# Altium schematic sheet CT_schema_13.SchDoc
size 391 x 385 mm
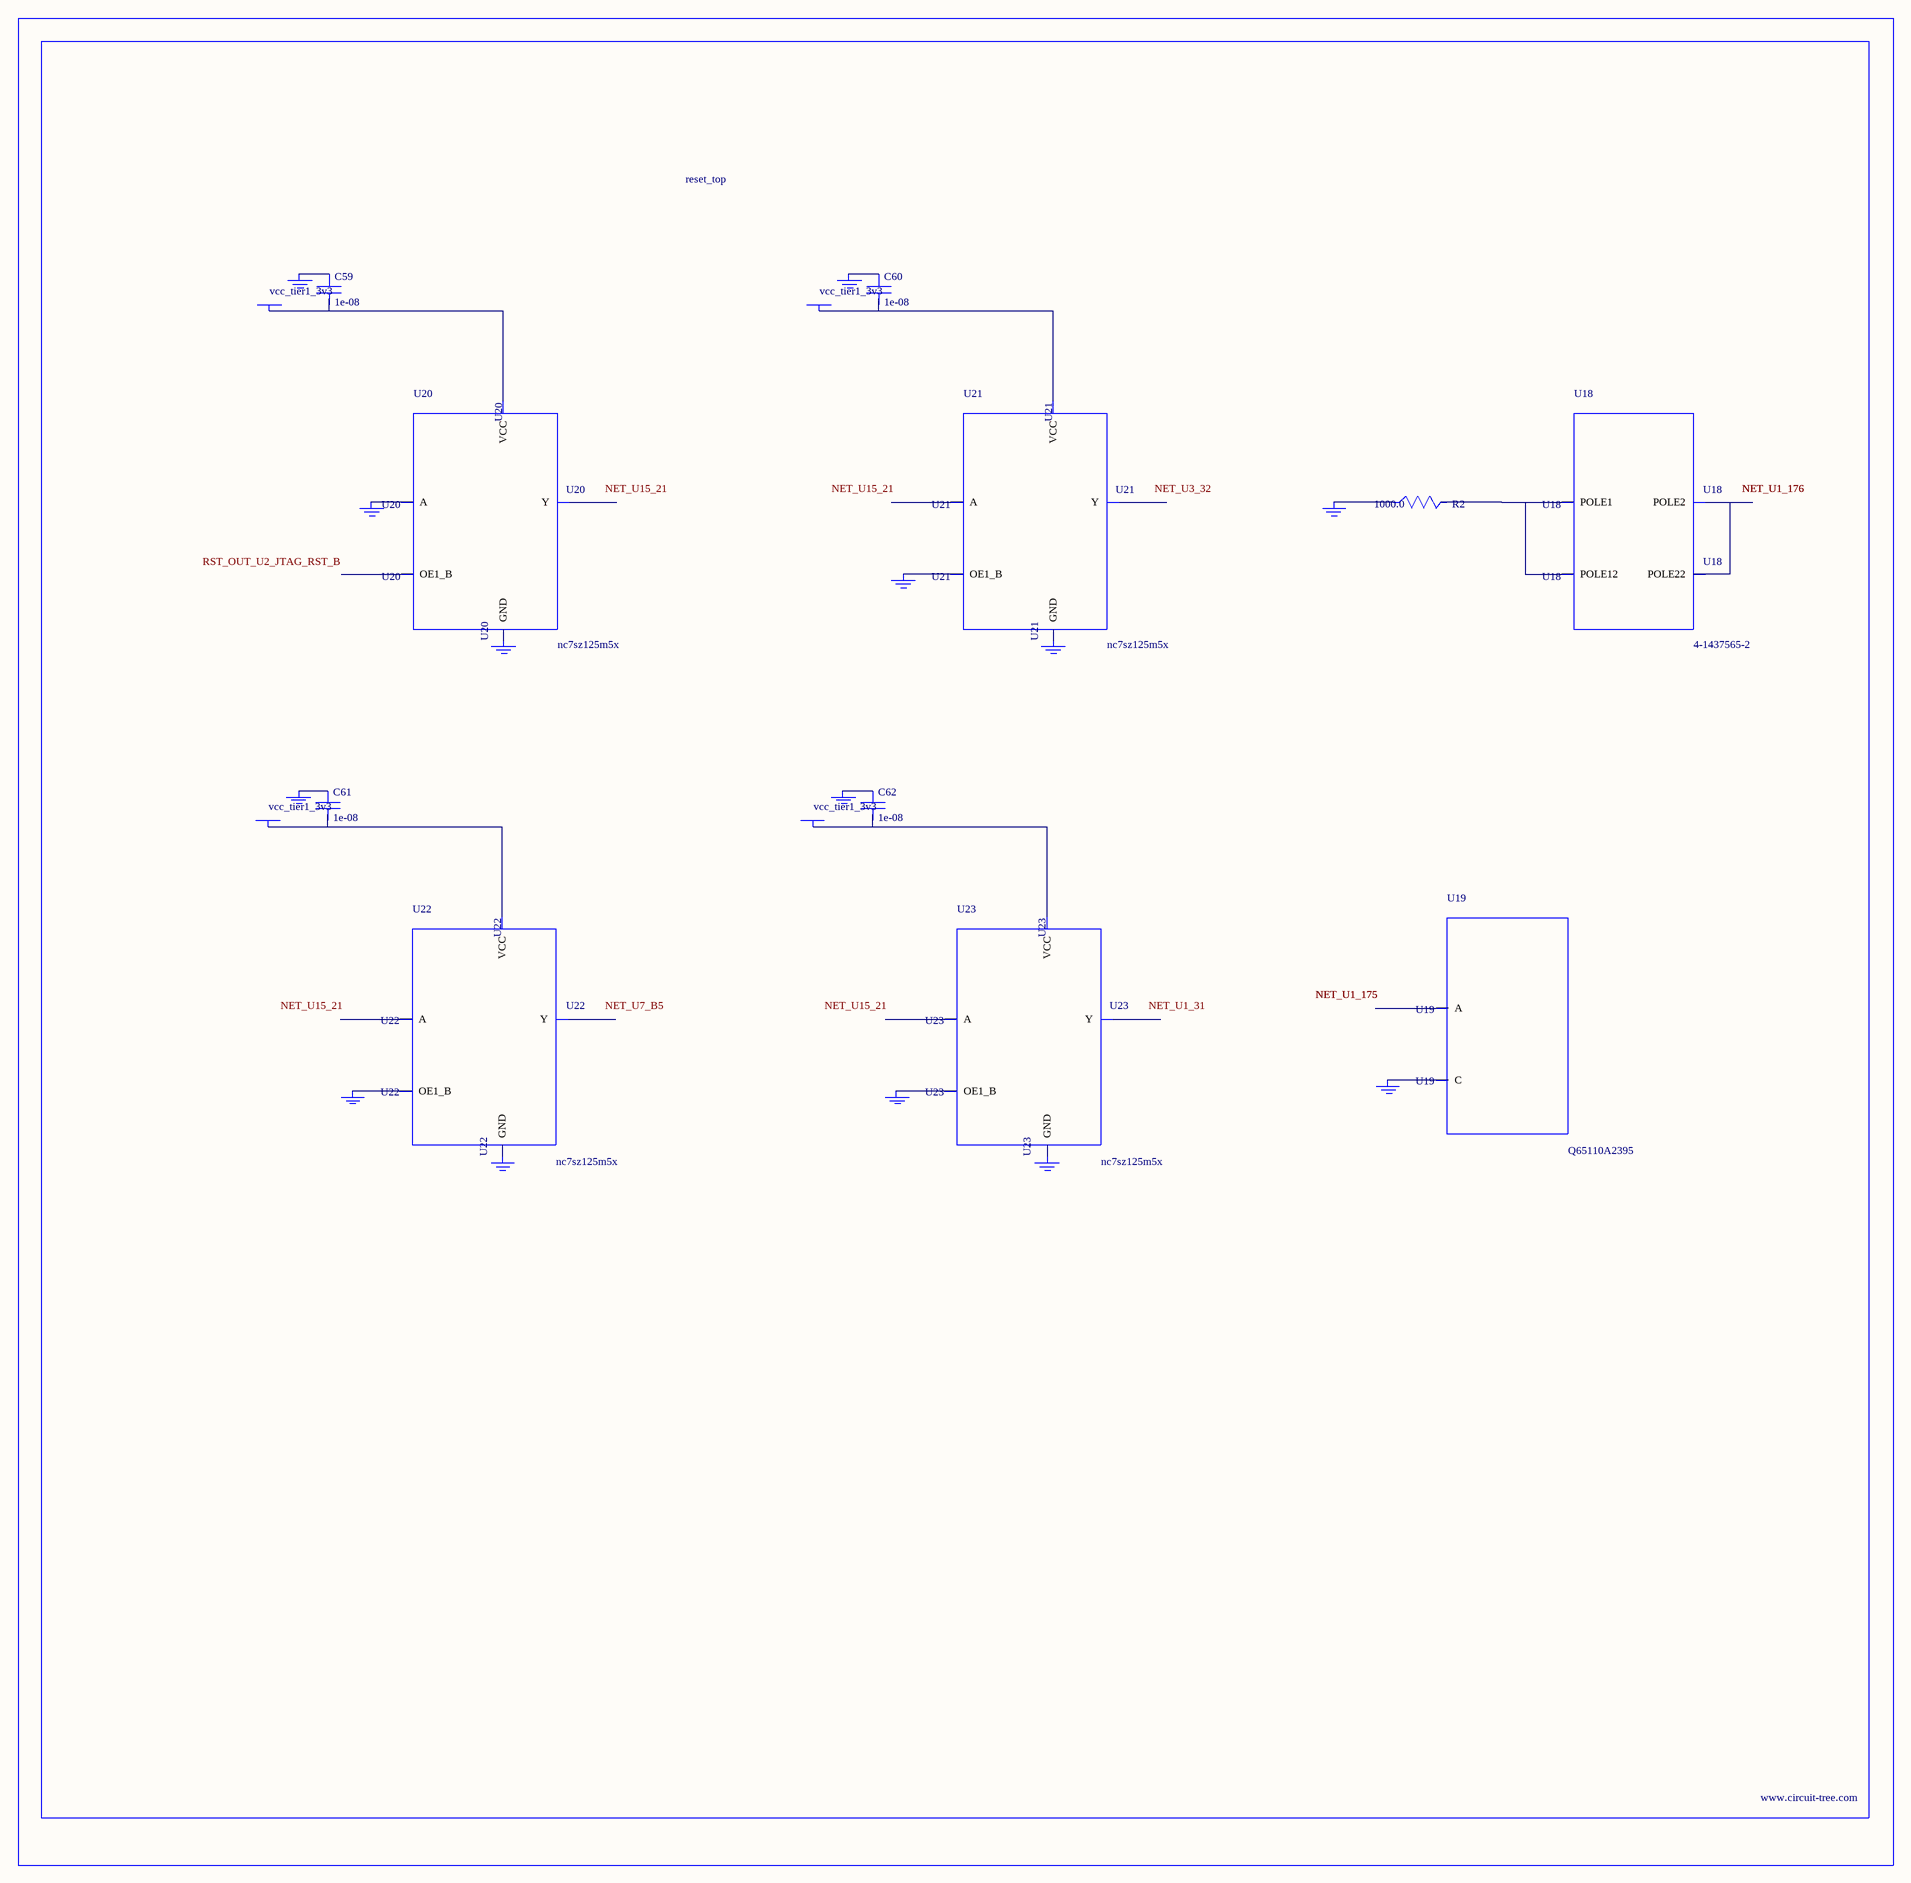
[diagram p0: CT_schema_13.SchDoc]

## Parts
BORDER12  (no value)
C59  1e-08  [C0402]
C60  1e-08  [C0402]
C61  1e-08  [C0402]
C62  1e-08  [C0402]
GND_INSTANCE_12_0  (no value)
GND_INSTANCE_12_1  (no value)
GND_INSTANCE_12_2  (no value)
GND_INSTANCE_12_3  (no value)
GND_INSTANCE_12_4  (no value)
GND_INSTANCE_12_5  (no value)
GND_INSTANCE_12_6  (no value)
GND_INSTANCE_12_7  (no value)
GND_INSTANCE_12_8  (no value)
GND_INSTANCE_12_9  (no value)
GND_INSTANCE_12_10  (no value)
GND_INSTANCE_12_11  (no value)
GND_INSTANCE_12_12  (no value)
GND_INSTANCE_12_13  (no value)
POWER_INSTANCE_12_0  vcc_tier1_3v3
POWER_INSTANCE_12_1  vcc_tier1_3v3
POWER_INSTANCE_12_2  vcc_tier1_3v3
POWER_INSTANCE_12_3  vcc_tier1_3v3
R2  1000.0  [R0603]
U18  4-1437565-2  [SW_4-1437565-2]
U19  Q65110A2395  [LGM67K-G1J2-24-Z]
U20  nc7sz125m5x  [NC7SZ125M5X]
U21  nc7sz125m5x  [NC7SZ125M5X]
U22  nc7sz125m5x  [NC7SZ125M5X]
U23  nc7sz125m5x  [NC7SZ125M5X]

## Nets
NetC59_1: C59.1 GND_INSTANCE_12_2.0(GND)
NetC59_2: C59.2 POWER_INSTANCE_12_0.0(PWR) U20.5(VCC)
NetC60_1: C60.1 GND_INSTANCE_12_5.0(GND)
NetC60_2: C60.2 POWER_INSTANCE_12_1.0(PWR) U21.5(VCC)
NetC61_1: C61.1 GND_INSTANCE_12_8.0(GND)
NetC61_2: C61.2 POWER_INSTANCE_12_2.0(PWR) U22.5(VCC)
NetC62_1: C62.1 GND_INSTANCE_12_11.0(GND)
NetC62_2: C62.2 POWER_INSTANCE_12_3.0(PWR) U23.5(VCC)
NetGND_INSTANCE_12_0_0: GND_INSTANCE_12_0.0(GND) R2.1
NetGND_INSTANCE_12_1_0: GND_INSTANCE_12_1.0(GND) U19.C
NetGND_INSTANCE_12_3_0: GND_INSTANCE_12_3.0(GND) U20.2(A)
NetGND_INSTANCE_12_4_0: GND_INSTANCE_12_4.0(GND) U20.3(GND)
NetGND_INSTANCE_12_6_0: GND_INSTANCE_12_6.0(GND) U21.1(OE1_B)
NetGND_INSTANCE_12_7_0: GND_INSTANCE_12_7.0(GND) U21.3(GND)
NetGND_INSTANCE_12_9_0: GND_INSTANCE_12_9.0(GND) U22.1(OE1_B)
NetGND_INSTANCE_12_10_0: GND_INSTANCE_12_10.0(GND) U22.3(GND)
NetGND_INSTANCE_12_12_0: GND_INSTANCE_12_12.0(GND) U23.1(OE1_B)
NetGND_INSTANCE_12_13_0: GND_INSTANCE_12_13.0(GND) U23.3(GND)
NetR2_2: R2.2 U18.1(POLE1) U18.2(POLE12)
NetU18_3: U18.3(POLE2) U18.4(POLE22)

Not connected (* = marked no-connect by the designer): U19 A; U20 1(OE1_B) 4(Y); U21 2(A) 4(Y); U22 2(A) 4(Y); U23 2(A) 4(Y)

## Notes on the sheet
- Labels drawn without touching a wire or pin: NET_U1_31, NET_U3_32, NET_U7_B5, NET_U15_21, RST_OUT_U2_JTAG_RST_B

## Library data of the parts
BORDER12 = BORDER_PAGE12
C59-C62 = C0402C103K3RAC
GND_INSTANCE_12_0-GND_INSTANCE_12_13 = GND
POWER_INSTANCE_12_0-POWER_INSTANCE_12_3 = PWR
R2 = RC0603JR-071KL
